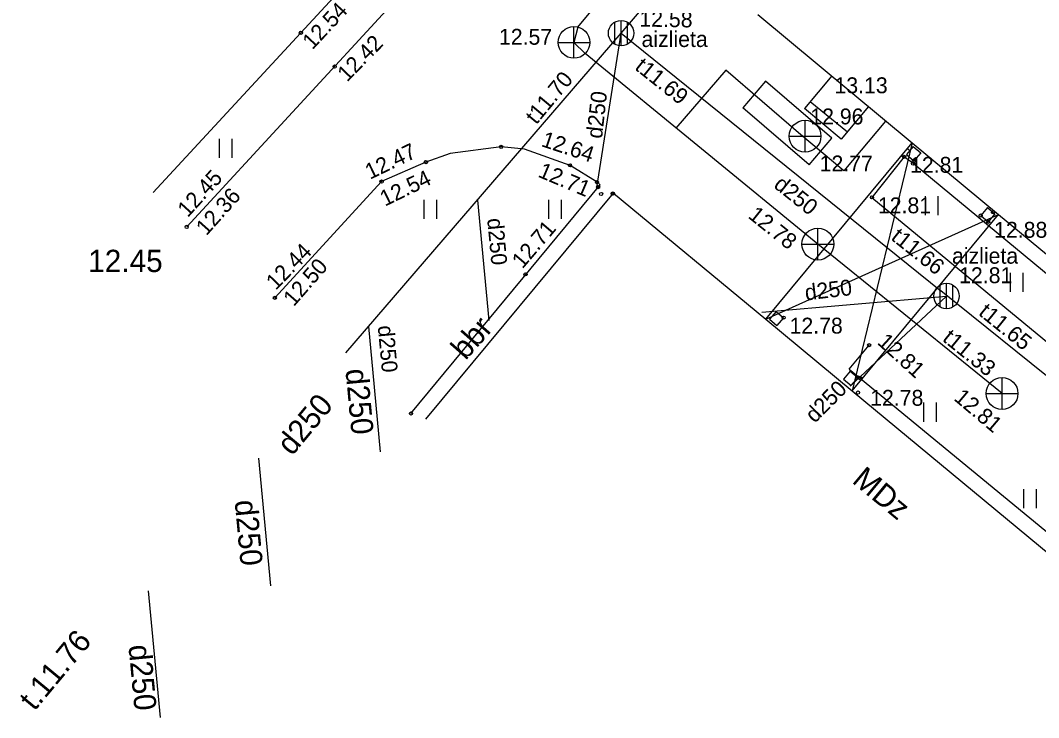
# Model space of a CAD drawing. Extents: x 503877 to 504025, y 304562 to 304725.
# Drawn here: x 503878.03 to 503910.05, y 304562.02 to 304583.96 of the extents above; entities that cross this region are included whole.
import ezdxf

# ---------------------------------------------------------------- set-up
doc = ezdxf.new("R2010")
doc.units = 0
for name, color, linetype in [('BUVE_BALK_####_####_#', 7, 'Continuous'), ('BUVE_BDET_####_####_#', 7, 'Continuous'), ('BUVE_EKAS_####_####_#', 7, 'Continuous'), ('BUVE_EKAS_ADRS_TKST_#', 7, 'Continuous'), ('CELI_CAPM_####_####_#', 7, 'Continuous'), ('CELI_CMAL_####_####_#', 7, 'Continuous'), ('CELI_CSEG_####_TKST_#', 7, 'Continuous'), ('LKAN_ELEM_####_####_#', 7, 'Continuous'), ('LKAN_ELEM_PAST_TKST_#', 7, 'Continuous'), ('LKAN_VADP_PAST_####_#', 7, 'Continuous'), ('LKAN_VADP_PAST_TKST_#', 7, 'Continuous'), ('NORB_ZOGS_ZSTP_####_#', 7, 'Continuous'), ('RELJ_AATZ_####_TKST_#', 7, 'Continuous'), ('RELJ_ELEM_####_####_#', 7, 'Continuous'), ('SKAN_DETP_PAST_####_#', 7, 'Continuous'), ('SKAN_ELEM_####_####_#', 7, 'Continuous'), ('SKAN_ELEM_PAST_TKST_#', 7, 'Continuous'), ('SKAN_VADP_PAST_####_#', 7, 'Continuous'), ('SKAN_VADP_PAST_TKST_#', 7, 'Continuous'), ('TERT_ELEM_####_####_#', 7, 'Continuous')]:
    doc.layers.add(name, color=color, linetype=linetype)

msp = doc.modelspace()

# ---------------------------------------------------------------- linework, layer by layer
at = {"layer": 'BUVE_BALK_####_####_#'}
for p, q in [((503901.469, 304574.559), (503906.078, 304580.111)), ((503906.078, 304580.111), (503904.187, 304572.307)), ((503901.469, 304574.559), (503908.794, 304577.857)), ((503904.187, 304572.307), (503908.794, 304577.857))]:
    msp.add_line(p, q, dxfattribs=at)
at = {"layer": 'BUVE_BDET_####_####_#'}
for p, q in [((503903.544, 304582.215), (503902.685, 304581.187)), ((503903.845, 304580.218), (503902.685, 304581.187)), ((503902.868, 304581.407), (503904.037, 304580.448)), ((503904.707, 304581.25), (503903.845, 304580.218)), ((503906.109, 304579.989), (503905.898, 304579.74)), ((503906.109, 304579.989), (503906.343, 304579.791)), ((503905.898, 304579.74), (503906.133, 304579.541)), ((503906.343, 304579.791), (503906.132, 304579.542)), ((503908.443, 304578.068), (503908.232, 304577.819)), ((503908.443, 304578.068), (503908.677, 304577.87)), ((503908.232, 304577.819), (503908.467, 304577.62)), ((503908.677, 304577.87), (503908.466, 304577.621)), ((503901.8, 304574.803), (503901.589, 304574.554)), ((503901.8, 304574.803), (503902.034, 304574.605)), ((503901.589, 304574.554), (503901.824, 304574.355)), ((503902.034, 304574.605), (503901.823, 304574.356)), ((503904.13, 304572.925), (503903.919, 304572.676)), ((503904.13, 304572.925), (503904.364, 304572.727)), ((503903.919, 304572.676), (503904.154, 304572.477)), ((503904.364, 304572.727), (503904.153, 304572.478))]:
    msp.add_line(p, q, dxfattribs=at)
at = {"layer": 'BUVE_EKAS_####_####_#'}
for p, q in [((503901.224, 304584.141), (503906.078, 304580.111)), ((503905.927, 304579.929), (503906.003, 304579.865)), ((503906.078, 304580.111), (503908.794, 304577.857)), ((503890.785, 304571.41), (503896.682, 304578.526)), ((503896.682, 304578.526), (503901.469, 304574.559)), ((503908.794, 304577.857), (503913.603, 304573.865)), ((503901.469, 304574.559), (503904.187, 304572.307)), ((503904.187, 304572.307), (503913.325, 304564.734))]:
    msp.add_line(p, q, dxfattribs=at)
at = {"layer": 'CELI_CAPM_####_####_#'}
for p, q in [((503923.377, 304620.99), (503883.259, 304577.462)), ((503893.151, 304579.979), (503891.549, 304579.769)), ((503893.879, 304579.908), (503893.151, 304579.979)), ((503895.315, 304579.397), (503893.879, 304579.908)), ((503891.549, 304579.769), (503890.782, 304579.501)), ((503890.782, 304579.501), (503889.389, 304578.888)), ((503896.164, 304578.868), (503895.315, 304579.397)), ((503889.389, 304578.888), (503886.031, 304575.229)), ((503896.264, 304578.787), (503896.164, 304578.868))]:
    msp.add_line(p, q, dxfattribs=at)
at = {"layer": 'CELI_CMAL_####_####_#'}
for p, q in [((503905.824, 304579.664), (503904.812, 304578.39)), ((503906.103, 304579.453), (503905.824, 304579.664)), ((503913.691, 304573.18), (503906.103, 304579.453)), ((503890.314, 304571.591), (503896.264, 304578.787)), ((503904.812, 304578.39), (503912.077, 304572.389)), ((503904.097, 304572.983), (503904.722, 304573.74)), ((503904.097, 304572.983), (503912.739, 304565.859))]:
    msp.add_line(p, q, dxfattribs=at)
at = {"layer": 'LKAN_ELEM_####_####_#'}
for p, q in [((503896.722, 304583.21), (503896.722, 304583.902)), ((503896.922, 304583.156), (503896.922, 304583.956)), ((503897.122, 304583.21), (503897.122, 304583.902)), ((503906.956, 304574.941), (503906.956, 304575.633)), ((503907.156, 304574.887), (503907.156, 304575.687)), ((503907.356, 304574.941), (503907.356, 304575.633))]:
    msp.add_line(p, q, dxfattribs=at)
for centre in [(503896.922, 304583.556), (503907.156, 304575.287)]:
    msp.add_circle(centre, 0.4, dxfattribs=at)
at = {"layer": 'LKAN_VADP_PAST_####_#'}
for p, q in [((503896.922, 304583.556), (503899.169, 304586.18)), ((503888.269, 304573.497), (503896.922, 304583.556)), ((503896.159, 304578.706), (503896.922, 304583.556)), ((503896.922, 304583.556), (503906.982, 304575.455)), ((503892.404, 304578.304), (503892.759, 304574.512)), ((503913.78, 304569.963), (503906.982, 304575.455)), ((503901.35, 304574.782), (503907.156, 304575.287)), ((503904.127, 304572.45), (503907.156, 304575.287)), ((503888.98, 304574.324), (503889.116, 304572.874)), ((503889.116, 304572.874), (503889.349, 304570.383)), ((503885.516, 304570.189), (503885.892, 304566.173)), ((503882.048, 304566.013), (503882.421, 304562.022))]:
    msp.add_line(p, q, dxfattribs=at)
at = {"layer": 'NORB_ZOGS_ZSTP_####_#'}
msp.add_line((503882.208, 304578.545), (503916.428, 304615.582), dxfattribs=at)
at = {"layer": 'RELJ_ELEM_####_####_#'}
for centre in [(503886.851, 304583.57), (503887.913, 304582.506), (503893.151, 304579.979), (503905.824, 304579.664), (503906.133, 304579.541), (503890.782, 304579.501), (503895.315, 304579.397), (503906.103, 304579.453), (503889.389, 304578.888), (503896.164, 304578.868), (503896.201, 304578.711), (503896.292, 304578.498), (503896.659, 304578.51), (503896.665, 304578.505), (503904.812, 304578.39), (503908.232, 304577.819), (503908.467, 304577.62), (503908.62, 304577.918), (503883.259, 304577.462), (503893.917, 304575.968), (503886.031, 304575.229), (503902.034, 304574.605), (503904.722, 304573.74), (503904.364, 304572.727), (503904.44, 304572.7), (503904.37, 304572.25), (503890.314, 304571.591)]:
    msp.add_circle(centre, 0.05, dxfattribs=at)
at = {"layer": 'SKAN_DETP_PAST_####_#'}
for p, q in [((503901.463, 304582.046), (503900.746, 304581.212)), ((503903.552, 304580.249), (503901.463, 304582.046)), ((503902.835, 304579.415), (503900.746, 304581.212)), ((503902.835, 304579.415), (503903.552, 304580.249))]:
    msp.add_line(p, q, dxfattribs=at)
at = {"layer": 'SKAN_ELEM_####_####_#'}
for p, q in [((503895.44, 304582.766), (503895.44, 304583.766)), ((503894.94, 304583.266), (503895.94, 304583.266)), ((503902.707, 304579.816), (503902.707, 304580.816)), ((503902.207, 304580.316), (503903.207, 304580.316)), ((503903.11, 304576.42), (503903.11, 304577.42)), ((503902.61, 304576.92), (503903.61, 304576.92)), ((503908.903, 304571.72), (503908.903, 304572.72)), ((503908.403, 304572.22), (503909.403, 304572.22))]:
    msp.add_line(p, q, dxfattribs=at)
for centre in [(503895.44, 304583.266), (503902.707, 304580.316), (503903.11, 304576.92), (503908.903, 304572.22)]:
    msp.add_circle(centre, 0.5, dxfattribs=at)
at = {"layer": 'SKAN_VADP_PAST_####_#'}
for p, q in [((503895.56, 304583.751), (503913.827, 304605.568)), ((503895.56, 304583.751), (503895.44, 304583.266)), ((503895.44, 304583.266), (503895.796, 304582.915)), ((503903.11, 304576.92), (503895.796, 304582.915)), ((503900.215, 304582.393), (503898.641, 304580.563)), ((503902.503, 304580.426), (503900.215, 304582.393)), ((503905.242, 304580.787), (503903.929, 304579.226)), ((503903.929, 304579.226), (503902.503, 304580.426)), ((503908.903, 304572.22), (503903.11, 304576.92))]:
    msp.add_line(p, q, dxfattribs=at)
at = {"layer": 'TERT_ELEM_####_####_#'}
for p, q in [((503884.291, 304579.631), (503884.291, 304580.231)), ((503884.691, 304579.631), (503884.691, 304580.231)), ((503890.731, 304577.715), (503890.731, 304578.315)), ((503891.131, 304577.715), (503891.131, 304578.315)), ((503894.648, 304577.715), (503894.648, 304578.315)), ((503895.048, 304577.715), (503895.048, 304578.315)), ((503906.497, 304577.829), (503906.497, 304578.429)), ((503906.897, 304577.829), (503906.897, 304578.429)), ((503909.166, 304575.419), (503909.166, 304576.019)), ((503909.566, 304575.419), (503909.566, 304576.019)), ((503906.445, 304571.334), (503906.445, 304571.934)), ((503906.845, 304571.334), (503906.845, 304571.934)), ((503909.584, 304568.611), (503909.584, 304569.211)), ((503909.984, 304568.611), (503909.984, 304569.211))]:
    msp.add_line(p, q, dxfattribs=at)

# ---------------------------------------------------------------- texts
at = {"layer": 'BUVE_EKAS_ADRS_TKST_#'}
msp.add_text('MDz', height=0.7, rotation=320.3503, dxfattribs=at).set_placement((503904.153, 304569.432))
at = {"layer": 'CELI_CSEG_####_TKST_#'}
msp.add_text('bbr', height=0.7, rotation=48.5338, dxfattribs=at).set_placement((503892.032, 304573.243))
at = {"layer": 'LKAN_ELEM_PAST_TKST_#'}
msp.add_text(' 12.58', height=0.5, rotation=359.0076, dxfattribs=at).set_placement((503897.307, 304583.769))
msp.add_text(' 12.81', height=0.5, dxfattribs=at).set_placement((503907.367, 304575.691))
at = {"layer": 'LKAN_VADP_PAST_TKST_#'}
for s, height, rotation, p in [('t11.69', 0.5, 321.3783, (503897.322, 304582.438)), ('t11.70', 0.5, 50.2872, (503894.253, 304580.657)), ('d250', 0.5, 83.6801, (503896.321, 304580.224)), ('d250', 0.5, 321.3783, (503901.689, 304578.726)), ('d250', 0.5, 275.344, (503892.709, 304577.717)), ('t11.66', 0.5, 321.3783, (503905.38, 304577.082)), ('d250', 0.5, 6.8143, (503902.731, 304575.145)), ('t11.65', 0.5, 321.0658, (503908.132, 304574.715)), ('d250', 0.5, 275.344, (503889.266, 304574.341)), ('d250', 0.7, 275.344, (503888.253, 304572.972)), ('d250', 0.5, 45.0673, (503903.012, 304571.268)), ('d250', 0.7, 50.2872, (503886.573, 304570.235)), ('d250', 0.7, 275.344, (503884.767, 304568.844)), ('t.11.76', 0.7, 50.2872, (503878.472, 304562.206)), ('d250', 0.7, 275.344, (503881.428, 304564.29))]:
    msp.add_text(s, height=height, rotation=rotation, dxfattribs=at).set_placement(p)
at = {"layer": 'RELJ_AATZ_####_TKST_#'}
for s, rotation, p in [(' 12.54', 46.9186, (503887.088, 304582.88)), (' 12.42', 45.6092, (503888.175, 304581.869)), (' 12.64', 341.6283, (503894.206, 304580.067)), (' 12.47', 25.677, (503888.854, 304578.861)), (' 12.45', 47.6551, (503883.167, 304577.599)), (' 12.71', 336.9836, (503894.108, 304579.122)), (' 12.54', 25.8637, (503889.324, 304578.014)), (' 12.36', 48.2135, (503883.753, 304577.023)), (' 12.71', 49.4288, (503893.699, 304575.982)), (' 12.44', 45.5202, (503885.931, 304575.318)), (' 12.50', 48.8083, (503886.504, 304574.794)), (' 12.81', 317.6006, (503904.814, 304573.924))]:
    msp.add_text(s, height=0.5, rotation=rotation, dxfattribs=at).set_placement(p)
for s, height, p in [(' 13.13', 0.5, (503903.447, 304581.667)), (' 12.96', 0.5, (503902.685, 304580.687)), (' 12.81', 0.5, (503905.824, 304579.164)), (' 12.81', 0.5, (503904.812, 304577.89)), (' 12.88', 0.5, (503908.467, 304577.12)), ('12.45', 0.7, (503880.162, 304576.042)), (' 12.78', 0.5, (503902.034, 304574.105)), (' 12.78', 0.5, (503904.569, 304571.834))]:
    msp.add_text(s, height=height, dxfattribs=at).set_placement(p)
at = {"layer": 'SKAN_ELEM_PAST_TKST_#'}
for s, p in [(' 12.57', (503892.895, 304583.193)), ('aizlieta', (503897.565, 304583.121)), (' 12.77', (503902.981, 304579.206)), ('aizlieta', (503907.328, 304576.303))]:
    msp.add_text(s, height=0.5, dxfattribs=at).set_placement(p)
for s, rotation, p in [(' 12.78', 321.3105, (503900.742, 304577.882)), (' 12.81', 319.8004, (503907.215, 304572.155))]:
    msp.add_text(s, height=0.5, rotation=rotation, dxfattribs=at).set_placement(p)
at = {"layer": 'SKAN_VADP_PAST_TKST_#'}
msp.add_text('t11.33', height=0.5, rotation=320.973, dxfattribs=at).set_placement((503906.997, 304573.899))

doc.saveas('drawing.dxf')
